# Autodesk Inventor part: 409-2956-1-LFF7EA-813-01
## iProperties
Created: 2010-11
Part Number: 409-2956-1-LFF7EA-813-01
Material: 3/8" OD TUBE - SS
Description: PT TUBING
Document SubType Name: Modeling
Designer: S. Boerckel
Engineer: Steve Boerckel
Mass: 769.029 g
Surface Area: 1665.99 cm^2
Volume: 95.1769 cm^3
Density: 8.08 g/cm^3
Length: 140.652 in
Author: S. Boerckel
Revision Number: 0
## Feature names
1. Sweep1
